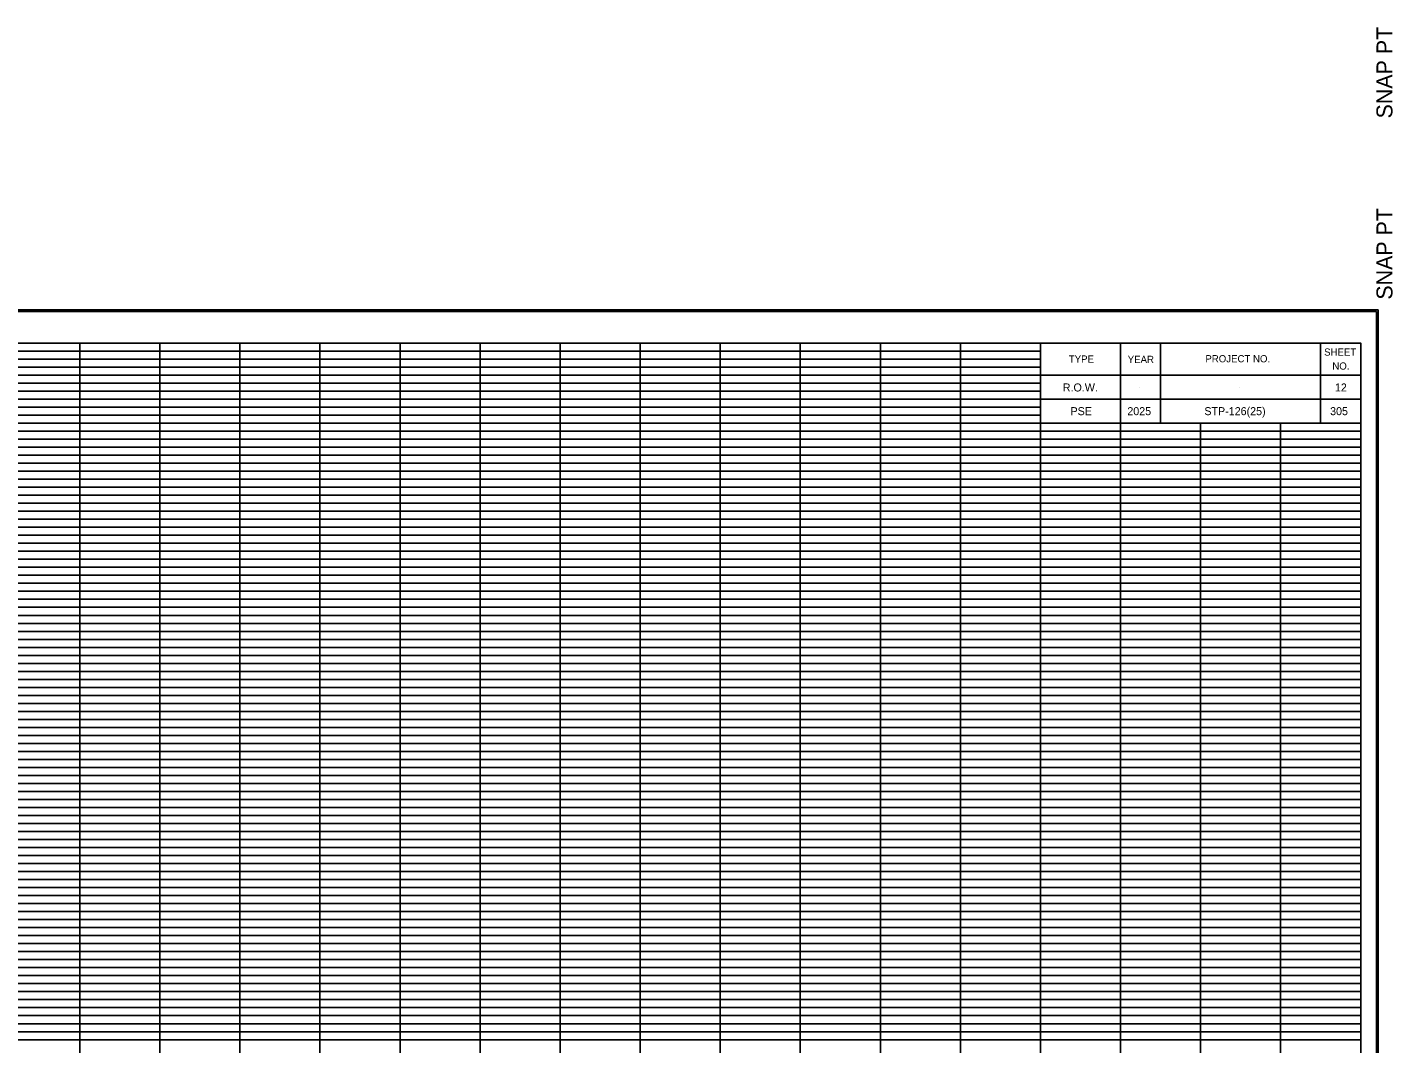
# Model space of a CAD drawing. Extents: x 980 to 2064, y 978 to 2267.
# Drawn here: x 1893.4 to 2064, y 1382.5 to 1509.4 of the extents above; entities that cross this region are included whole.
import ezdxf

# ---------------------------------------------------------------- set-up
doc = ezdxf.new("R2010")
doc.units = 0
for name, color, linetype in [('Default', 7, 'Continuous'), ('DESIGN - SCRATCH - User 1', 7, 'Continuous'), ('DESIGN - SHEET - Corner Text', 7, 'Continuous'), ('DESIGN - SHEET - Light Grid', 7, 'Continuous'), ('DESIGN - SHEET - Linework', 7, 'Continuous'), ('DESIGN - SHEET - Plot Shape', 7, 'Continuous')]:
    doc.layers.add(name, color=color, linetype=linetype)

# ---------------------------------------------------------------- blocks, each defined once
blk = doc.blocks.new('XSTSHT')
at = {"layer": 'DESIGN - SCRATCH - User 1'}
for p, q in [((28.5, 20.45), (28.5, 20.45)), ((29.24, 20.45), (29.24, 20.45)), ((30.49, 20.45), (30.49, 20.45)), ((31.74, 20.45), (31.74, 20.45)), ((28.5, 20.15), (28.5, 20.15)), ((29.24, 20.15), (29.24, 20.15)), ((30.49, 20.15), (30.49, 20.15)), ((31.74, 20.15), (31.74, 20.15))]:
    blk.add_line(p, q, dxfattribs=at)
at = {"layer": 'DESIGN - SHEET - Light Grid'}
for p, q in [((8, 20.9), (16, 20.9)), ((16, 20.9), (24, 20.9)), ((24, 20.9), (28, 20.9)), ((8, 20.8), (16, 20.8)), ((8, 20.7), (16, 20.7)), ((16, 20.8), (24, 20.8)), ((16, 20.7), (24, 20.7)), ((24, 20.8), (28, 20.8)), ((24, 20.7), (28, 20.7)), ((8, 20.6), (16, 20.6)), ((8, 20.5), (16, 20.5)), ((16, 20.6), (24, 20.6)), ((16, 20.5), (24, 20.5)), ((24, 20.6), (28, 20.6)), ((24, 20.5), (28, 20.5)), ((8, 20.4), (16, 20.4)), ((8, 20.3), (16, 20.3)), ((16, 20.4), (24, 20.4)), ((16, 20.3), (24, 20.3)), ((24, 20.4), (28, 20.4)), ((24, 20.3), (28, 20.3)), ((8, 20.2), (16, 20.2)), ((16, 20.2), (24, 20.2)), ((24, 20.2), (28, 20.2)), ((8, 20.1), (16, 20.1)), ((16, 20.1), (24, 20.1)), ((24, 20.1), (28, 20.1)), ((8, 19.9), (16, 19.9)), ((8, 19.8), (16, 19.8)), ((16, 19.9), (24, 19.9)), ((16, 19.8), (24, 19.8)), ((24, 19.9), (32, 19.9)), ((24, 19.8), (32, 19.8)), ((8, 19.7), (16, 19.7)), ((16, 19.7), (24, 19.7)), ((24, 19.7), (32, 19.7)), ((8, 19.6), (16, 19.6)), ((8, 19.5), (16, 19.5)), ((16, 19.6), (24, 19.6)), ((16, 19.5), (24, 19.5)), ((24, 19.6), (32, 19.6)), ((24, 19.5), (32, 19.5)), ((8, 19.4), (16, 19.4)), ((8, 19.3), (16, 19.3)), ((16, 19.4), (24, 19.4)), ((16, 19.3), (24, 19.3)), ((24, 19.4), (32, 19.4)), ((24, 19.3), (32, 19.3)), ((8, 19.2), (16, 19.2)), ((16, 19.2), (24, 19.2)), ((24, 19.2), (32, 19.2)), ((8, 19.1), (16, 19.1)), ((16, 19.1), (24, 19.1)), ((24, 19.1), (32, 19.1)), ((8, 18.9), (16, 18.9)), ((8, 18.8), (16, 18.8)), ((16, 18.9), (24, 18.9)), ((16, 18.8), (24, 18.8)), ((24, 18.9), (32, 18.9)), ((24, 18.8), (32, 18.8)), ((8, 18.7), (16, 18.7)), ((8, 18.6), (16, 18.6)), ((16, 18.7), (24, 18.7)), ((16, 18.6), (24, 18.6)), ((24, 18.7), (32, 18.7)), ((24, 18.6), (32, 18.6)), ((8, 18.5), (16, 18.5)), ((16, 18.5), (24, 18.5)), ((24, 18.5), (32, 18.5)), ((8, 18.4), (16, 18.4)), ((8, 18.3), (16, 18.3)), ((16, 18.4), (24, 18.4)), ((16, 18.3), (24, 18.3)), ((24, 18.4), (32, 18.4)), ((24, 18.3), (32, 18.3)), ((8, 18.2), (16, 18.2)), ((8, 18.1), (16, 18.1)), ((16, 18.2), (24, 18.2)), ((16, 18.1), (24, 18.1)), ((24, 18.2), (32, 18.2)), ((24, 18.1), (32, 18.1)), ((8, 17.9), (16, 17.9)), ((8, 17.8), (16, 17.8)), ((16, 17.9), (24, 17.9)), ((16, 17.8), (24, 17.8)), ((24, 17.9), (32, 17.9)), ((24, 17.8), (32, 17.8)), ((8, 17.7), (16, 17.7)), ((8, 17.6), (16, 17.6)), ((16, 17.7), (24, 17.7)), ((16, 17.6), (24, 17.6)), ((24, 17.7), (32, 17.7)), ((24, 17.6), (32, 17.6)), ((8, 17.5), (16, 17.5)), ((8, 17.4), (16, 17.4)), ((16, 17.5), (24, 17.5)), ((16, 17.4), (24, 17.4)), ((24, 17.5), (32, 17.5)), ((24, 17.4), (32, 17.4)), ((8, 17.3), (16, 17.3)), ((16, 17.3), (24, 17.3)), ((24, 17.3), (32, 17.3)), ((8, 17.2), (16, 17.2)), ((8, 17.1), (16, 17.1)), ((16, 17.2), (24, 17.2)), ((16, 17.1), (24, 17.1)), ((24, 17.2), (32, 17.2)), ((24, 17.1), (32, 17.1)), ((8, 16.9), (16, 16.9)), ((16, 16.9), (24, 16.9)), ((24, 16.9), (32, 16.9)), ((8, 16.8), (16, 16.8)), ((16, 16.8), (24, 16.8)), ((24, 16.8), (32, 16.8)), ((8, 16.7), (16, 16.7)), ((8, 16.6), (16, 16.6)), ((16, 16.7), (24, 16.7)), ((16, 16.6), (24, 16.6)), ((24, 16.7), (32, 16.7)), ((24, 16.6), (32, 16.6)), ((8, 16.5), (16, 16.5)), ((8, 16.4), (16, 16.4)), ((16, 16.5), (24, 16.5)), ((16, 16.4), (24, 16.4)), ((24, 16.5), (32, 16.5)), ((24, 16.4), (32, 16.4)), ((8, 16.3), (16, 16.3)), ((16, 16.3), (24, 16.3)), ((24, 16.3), (32, 16.3)), ((8, 16.2), (16, 16.2)), ((8, 16.1), (16, 16.1)), ((16, 16.2), (24, 16.2)), ((16, 16.1), (24, 16.1)), ((24, 16.2), (32, 16.2)), ((24, 16.1), (32, 16.1)), ((8, 15.9), (16, 15.9)), ((16, 15.9), (24, 15.9)), ((24, 15.9), (32, 15.9)), ((8, 15.8), (16, 15.8)), ((8, 15.7), (16, 15.7)), ((16, 15.8), (24, 15.8)), ((16, 15.7), (24, 15.7)), ((24, 15.8), (32, 15.8)), ((24, 15.7), (32, 15.7)), ((8, 15.6), (16, 15.6)), ((16, 15.6), (24, 15.6)), ((24, 15.6), (32, 15.6)), ((8, 15.5), (16, 15.5)), ((8, 15.4), (16, 15.4)), ((16, 15.5), (24, 15.5)), ((16, 15.4), (24, 15.4)), ((24, 15.5), (32, 15.5)), ((24, 15.4), (32, 15.4)), ((8, 15.3), (16, 15.3)), ((8, 15.2), (16, 15.2)), ((16, 15.3), (24, 15.3)), ((16, 15.2), (24, 15.2)), ((24, 15.3), (32, 15.3)), ((24, 15.2), (32, 15.2)), ((8, 15.1), (16, 15.1)), ((16, 15.1), (24, 15.1)), ((24, 15.1), (32, 15.1)), ((8, 14.9), (16, 14.9)), ((16, 14.9), (24, 14.9)), ((24, 14.9), (32, 14.9)), ((8, 14.8), (16, 14.8)), ((8, 14.7), (16, 14.7)), ((16, 14.8), (24, 14.8)), ((16, 14.7), (24, 14.7)), ((24, 14.8), (32, 14.8)), ((24, 14.7), (32, 14.7)), ((8, 14.6), (16, 14.6)), ((8, 14.5), (16, 14.5)), ((16, 14.6), (24, 14.6)), ((16, 14.5), (24, 14.5)), ((24, 14.6), (32, 14.6)), ((24, 14.5), (32, 14.5)), ((8, 14.4), (16, 14.4)), ((16, 14.4), (24, 14.4)), ((24, 14.4), (32, 14.4)), ((8, 14.3), (16, 14.3)), ((8, 14.2), (16, 14.2)), ((16, 14.3), (24, 14.3)), ((16, 14.2), (24, 14.2)), ((24, 14.3), (32, 14.3)), ((24, 14.2), (32, 14.2)), ((8, 14.1), (16, 14.1)), ((16, 14.1), (24, 14.1)), ((24, 14.1), (32, 14.1)), ((8, 13.9), (16, 13.9)), ((16, 13.9), (24, 13.9)), ((24, 13.9), (32, 13.9)), ((8, 13.8), (16, 13.8)), ((8, 13.7), (16, 13.7)), ((16, 13.8), (24, 13.8)), ((16, 13.7), (24, 13.7)), ((24, 13.8), (32, 13.8)), ((24, 13.7), (32, 13.7)), ((8, 13.6), (16, 13.6)), ((8, 13.5), (16, 13.5)), ((16, 13.6), (24, 13.6)), ((16, 13.5), (24, 13.5)), ((24, 13.6), (32, 13.6)), ((24, 13.5), (32, 13.5)), ((8, 13.4), (16, 13.4)), ((16, 13.4), (24, 13.4)), ((24, 13.4), (32, 13.4)), ((8, 13.3), (16, 13.3)), ((8, 13.2), (16, 13.2)), ((16, 13.3), (24, 13.3)), ((16, 13.2), (24, 13.2)), ((24, 13.3), (32, 13.3)), ((24, 13.2), (32, 13.2)), ((8, 13.1), (16, 13.1)), ((16, 13.1), (24, 13.1)), ((24, 13.1), (32, 13.1)), ((8, 12.9), (16, 12.9)), ((8, 12.8), (16, 12.8)), ((16, 12.9), (24, 12.9)), ((16, 12.8), (24, 12.8)), ((24, 12.9), (32, 12.9)), ((24, 12.8), (32, 12.8)), ((8, 12.7), (16, 12.7)), ((16, 12.7), (24, 12.7)), ((24, 12.7), (32, 12.7)), ((8, 12.6), (16, 12.6)), ((8, 12.5), (16, 12.5)), ((16, 12.6), (24, 12.6)), ((16, 12.5), (24, 12.5)), ((24, 12.6), (32, 12.6)), ((24, 12.5), (32, 12.5)), ((8, 12.4), (16, 12.4)), ((8, 12.3), (16, 12.3)), ((16, 12.4), (24, 12.4)), ((16, 12.3), (24, 12.3)), ((24, 12.4), (32, 12.4)), ((24, 12.3), (32, 12.3))]:
    blk.add_line(p, q, dxfattribs=at)
at = {"layer": 'DESIGN - SHEET - Linework'}
for p, q in [((-1.823, 21.414), (32.217, 21.414)), ((32.217, 21.414), (32.217, -0.414)), ((16, 0), (16, 21)), ((17, 0), (17, 21)), ((18, 0), (18, 21)), ((19, 0), (19, 21)), ((20, 0), (20, 21)), ((21, 0), (21, 21)), ((22, 0), (22, 21)), ((23, 0), (23, 21)), ((24, 0), (24, 21)), ((25, 0), (25, 21)), ((26, 0), (26, 21)), ((27, 0), (27, 21)), ((0, 20), (28, 20)), ((28, 0), (28, 20)), ((29, 0), (29, 20)), ((30, 0), (30, 20)), ((31, 0), (31, 20)), ((0, 19), (32, 19)), ((0, 18), (32, 18)), ((0, 17), (32, 17)), ((0, 16), (32, 16)), ((0, 15), (32, 15)), ((0, 14), (32, 14)), ((0, 13), (32, 13))]:
    blk.add_line(p, q, dxfattribs=at)
for points in [[(0, 21), (0, 0), (32, 0), (32, 21), (0, 21)], [(28, 21), (28, 20), (32, 20), (32, 21), (31.5, 21), (31.5, 20), (29.5, 20), (29.5, 21), (29, 21), (29, 20), (32, 20), (28, 20), (28, 20.3), (32, 20.3), (32, 20.6), (28, 20.6)]]:
    blk.add_lwpolyline(points, dxfattribs=at)
at = {"layer": 'DESIGN - SHEET - Plot Shape'}
for points in [[(-1.803, 21.394), (32.197, 21.394), (32.197, -0.394), (-1.803, -0.394)], [(-0.85, 21), (32, 21), (32, -0.25), (-0.85, -0.25)]]:
    blk.add_lwpolyline(points, close=True, dxfattribs=at)
at = {"layer": 'DESIGN - SHEET - Corner Text'}
for s, p in [('  SNAP PT', (32.397, 21.394)), ('SNAP PT  ', (32.397, -2.194))]:
    blk.add_text(s, height=0.2, rotation=90, dxfattribs=at).set_placement(p)
for s, p in [('TYPE', (28.354, 20.756)), ('YEAR', (29.09, 20.752)), ('PROJECT NO.', (30.06, 20.76)), ('SHEET', (31.543, 20.843)), ('NO.', (31.646, 20.669))]:
    blk.add_text(s, height=0.09, dxfattribs=at).set_placement(p)

msp = doc.modelspace()

# ---------------------------------------------------------------- block references
at = {"layer": 'Default', "xscale": 10, "yscale": 10}
for p in [(1740, 1520), (1740, 1260)]:
    msp.add_blockref('XSTSHT', p, dxfattribs=at)

# ---------------------------------------------------------------- texts
at = {"layer": 'DESIGN - SHEET - Corner Text'}
for s, p in [('R.O.W.', (2022.79, 1463.96)), ('12', (2056.78, 1463.96)), ('PSE', (2023.75, 1461)), ('2025', (2030.85, 1461)), ('STP-126(25)', (2040.47, 1461)), ('305', (2056.18, 1461))]:
    msp.add_text(s, height=1, dxfattribs=at).set_placement(p)

doc.saveas('drawing.dxf')
